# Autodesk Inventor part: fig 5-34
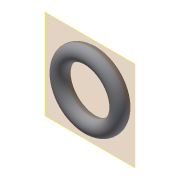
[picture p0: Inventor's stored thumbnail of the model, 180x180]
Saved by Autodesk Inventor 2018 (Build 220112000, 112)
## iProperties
Created: 2010-02
Part Number: fig 5-34
Document SubType Name: Modeling
Designer: CADSoft
Density: 1 g/cm^3
Material: Generic
Appearance: Default
Author: CADSoft
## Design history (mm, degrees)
sketch "Sketch1"
  geometry: L1 (0, 21.37)-(0, -16.247); C1 r 5 at (20.026, 0); 1 further point
  constraints: 2 end point, 1 centre point
  dimensions: "d0" = 10 diameter of C1
revolve "Revolution1" sketch "Sketch1" stored, may be unused: angle "d1" = 90 deg
workplane "Work Plane1"
body "Solid1"
